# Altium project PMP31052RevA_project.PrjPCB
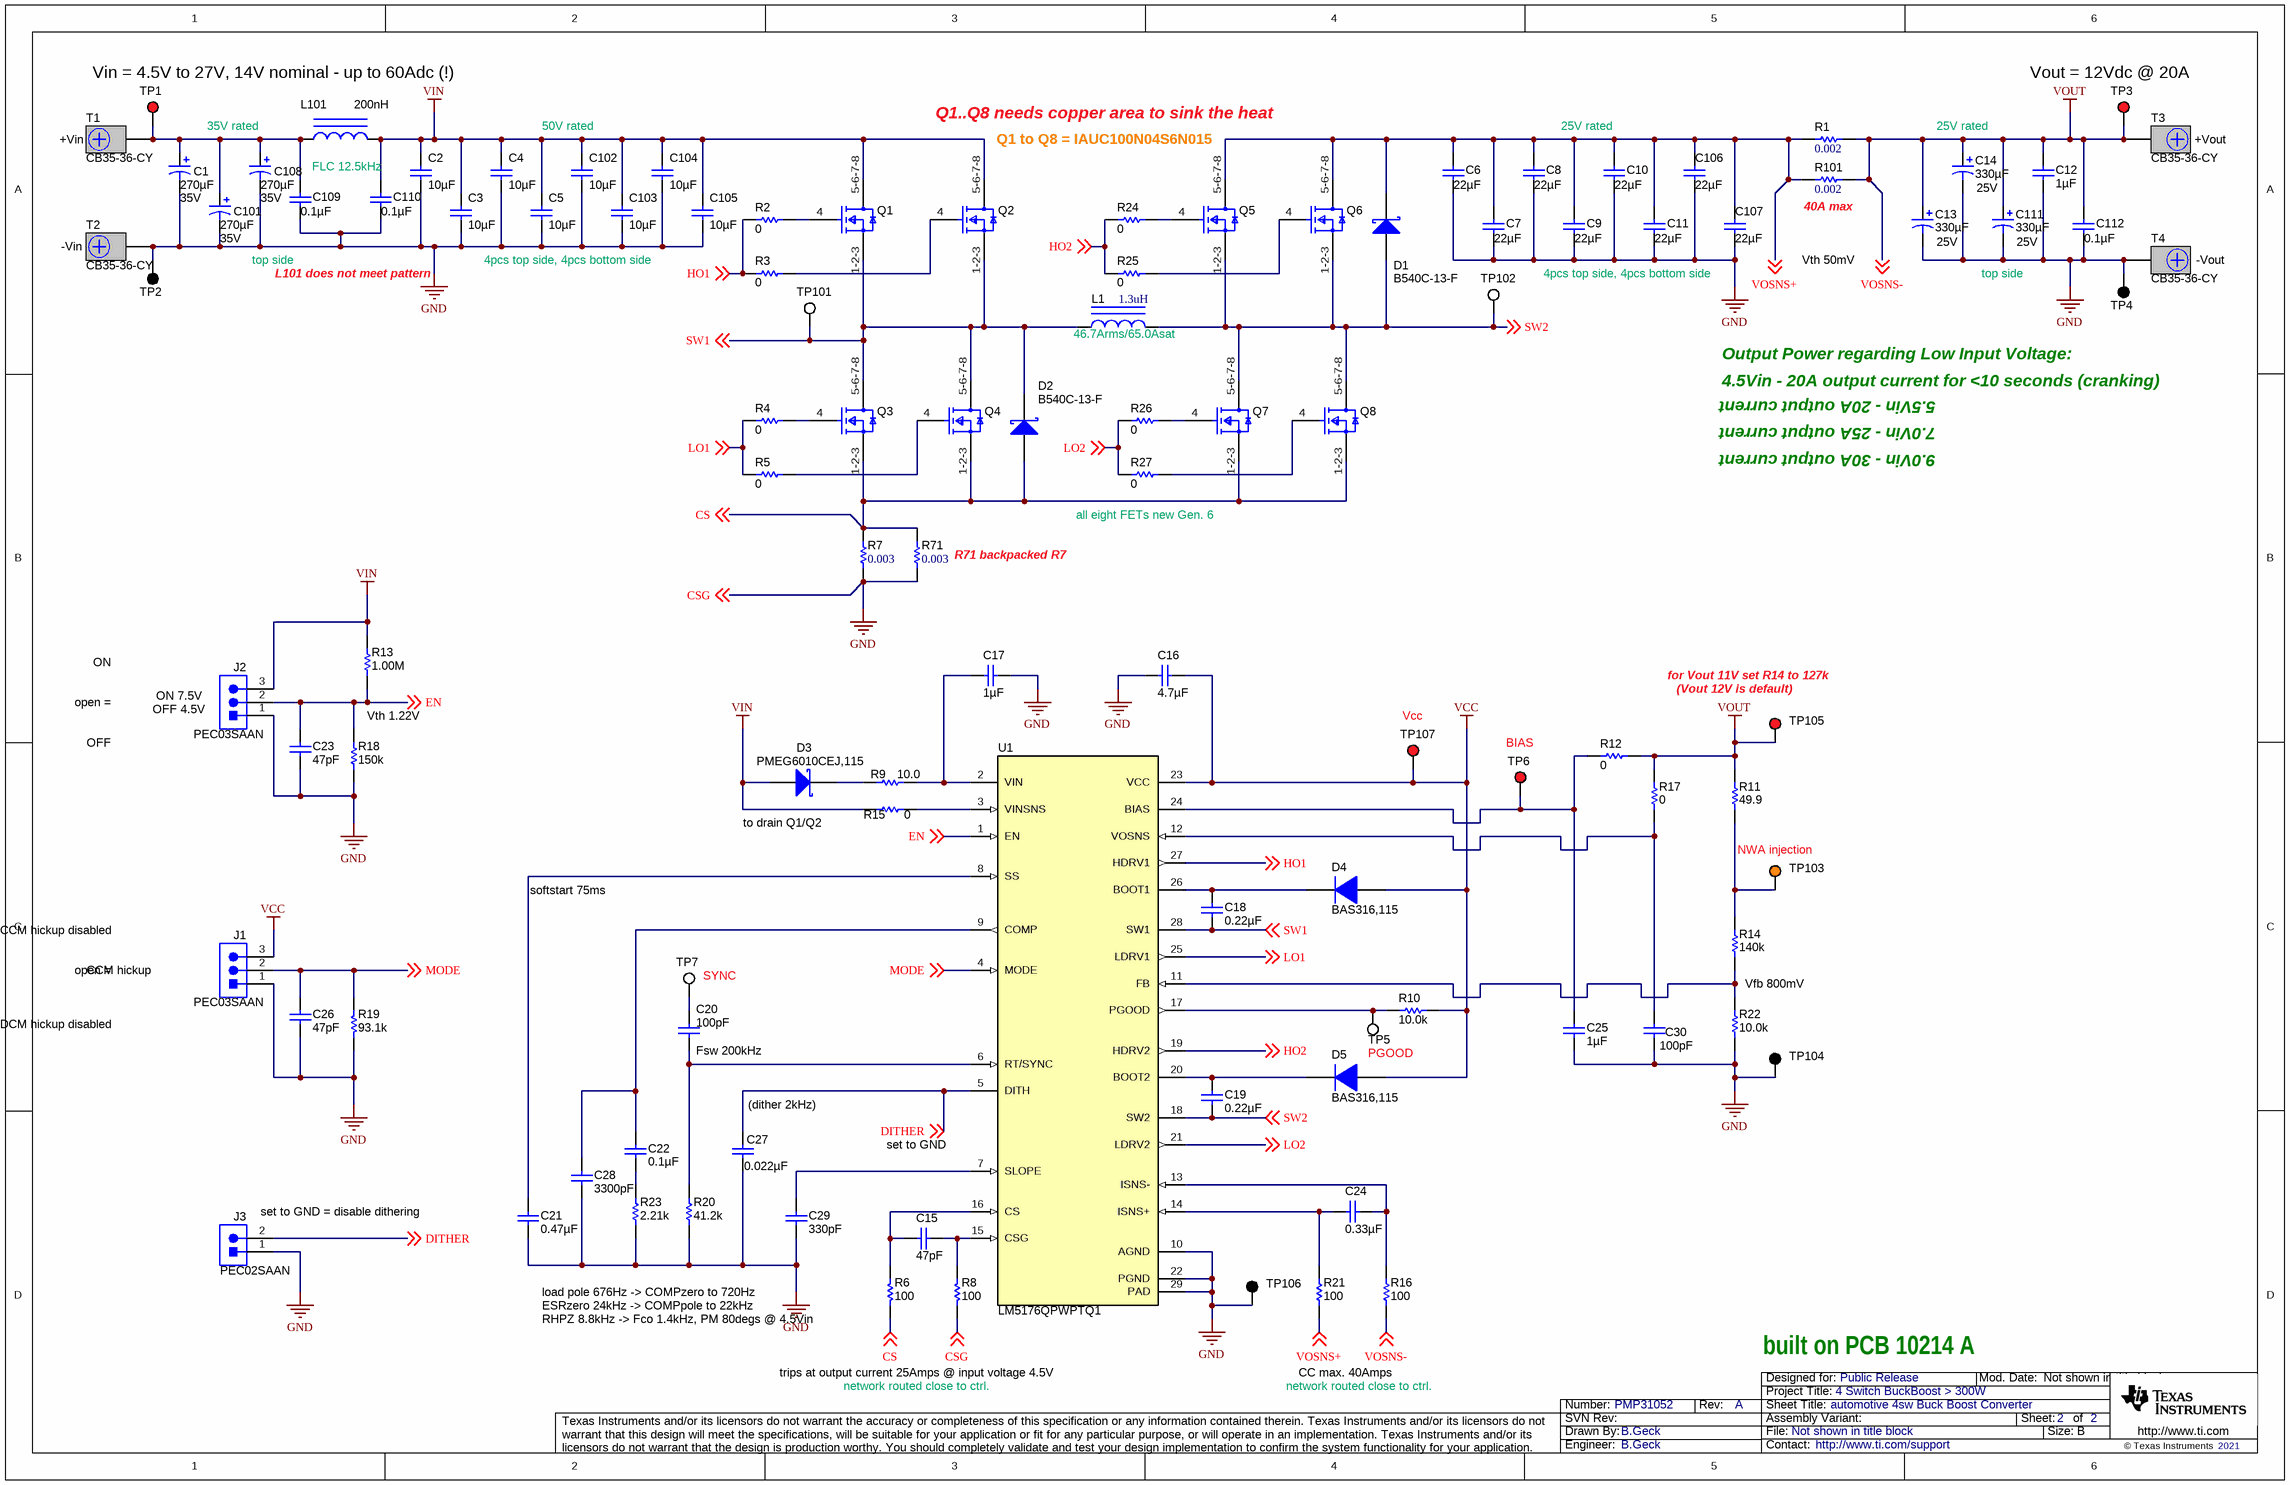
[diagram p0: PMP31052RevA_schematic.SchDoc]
TechSupport: http://www.ti.com/support; SCH_Rev: A; PRJ_Title: 4 Switch BuckBoost > 300W; PRJ_Number: PMP31052; PRJ_Engineer: B.Geck; PRJ_Customer: Public Release; PCB_Rev: A; PCB_Layout: PMP10214; CopyrightYear: 2021
2 sheets, 123 parts. Net scope: global (net labels, ports and power ports of the same name join across sheets).
Board file: PMP10214RevA_board.PcbDoc
Sheets:
  PMP31052RevA_schematic.SchDoc
  PMP31052RevA-HW.SchDoc

## Sheet PMP31052RevA_schematic.SchDoc: automotive 4sw Buck Boost Converter
size 431 x 279 mm; Date: Not shown in title block; ApprovedBy: Not shown in title block; CheckedBy: Not shown in title block; Author: Not shown in title block; CompanyName: Not shown in title block; DrawnBy: B.Geck; Engineer: B.Geck; Organization: Not shown in title block; Address1: Not shown in title block; Address2: Not shown in title block; Address3: Not shown in title block; Address4: Not shown in title block; DocumentNumber: 2; Revision: Use project parameter SCH_Rev; SheetNumber: 2; SheetTotal: 2; PageSetup: Record=PageOptions¦CenterHorizontal=True¦CenterVertical=True¦PrintScale=0.62¦XCorrection=1.00¦YCorrection=1.00¦PrintKind=0¦BorderSize=5000000¦LeftOffset=0¦BottomOffset=0¦Orientation=2¦PaperLength=1000¦PaperWidth=1000¦Scale=100¦PaperSource=15¦PrintQuality=600¦MediaType=1¦DitherType=10¦PrintScaleMode=1¦PaperKind=Letter

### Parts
C1  ValueDisplayed: 270µF  Value2: 35V  [SM_RADIAL_10BMM]  (hidden comment: EEHZC1V271P)
C2  ValueDisplayed: 10µF  [1210]  (hidden comment: GRM32ER71H106KA12L)
C3  ValueDisplayed: 10µF  [1210]  (hidden comment: GRM32ER71H106KA12L)
C4  ValueDisplayed: 10µF  [1210]  (hidden comment: GRM32ER71H106KA12L)
C5  ValueDisplayed: 10µF  [1210]  (hidden comment: GRM32ER71H106KA12L)
C6  ValueDisplayed: 22µF  [1210]  (hidden comment: GRM32ER71E226KE15L)
C7  ValueDisplayed: 22µF  [1210]  (hidden comment: GRM32ER71E226KE15L)
C8  ValueDisplayed: 22µF  [1210]  (hidden comment: GRM32ER71E226KE15L)
C9  ValueDisplayed: 22µF  [1210]  (hidden comment: GRM32ER71E226KE15L)
C10  ValueDisplayed: 22µF  [1210]  (hidden comment: GRM32ER71E226KE15L)
C11  ValueDisplayed: 22µF  [1210]  (hidden comment: GRM32ER71E226KE15L)
C12  ValueDisplayed: 1µF  [0805_HV]  (hidden comment: GRM219R71E105KA88D)
C13  ValueDisplayed: 330µF  Value2: 25V  [SM_RADIAL_10BMM]  (hidden comment: EEHZC1E331P)
C14  ValueDisplayed: 330µF  Value2: 25V  [SM_RADIAL_10BMM]  (hidden comment: EEHZC1E331P)
C15  ValueDisplayed: 47pF  [0603L]  (hidden comment: GRM1885C1H470JA01D)
C16  ValueDisplayed: 4.7µF  [0805_HV]  (hidden comment: GRM21BR71C475KA73L)
C17  ValueDisplayed: 1µF  [0603]  (hidden comment: GRM188R61H105KAALD)
C18  ValueDisplayed: 0.22µF  [0603L]  (hidden comment: GRM188R71E224KA88D)
C19  ValueDisplayed: 0.22µF  [0603L]  (hidden comment: GRM188R71E224KA88D)
C20  ValueDisplayed: 100pF  [0603L]  (hidden comment: GRM1885C2A101JA01D)
C21  ValueDisplayed: 0.47µF  [0603L]  (hidden comment: GRM188R71C474KA88D)
C22  ValueDisplayed: 0.1µF  [0603]  (hidden comment: GRM188R71E104KA01D)
C23  47pF  [0603L]
C24  ValueDisplayed: 0.33µF  [0603L]  (hidden comment: GRM188R71C334KA01D)
C25  ValueDisplayed: 1µF  [0603]  (hidden comment: GRM188R61H105KAALD)
C26  47pF  [0603L]
C27  ValueDisplayed: 0.022µF  [0603L]  (hidden comment: C0603C223K5RACTU)
C28  ValueDisplayed: 3300pF  [0603]  (hidden comment: GRM188R71E332KA01D)
C29  ValueDisplayed: 330pF  [0603]  (hidden comment: GRM188R71H331KA01D)
C30  ValueDisplayed: 100pF  [0603L]  (hidden comment: GRM1885C2A101JA01D)
C101  ValueDisplayed: 270µF  Value2: 35V  [SM_RADIAL_10BMM]  (hidden comment: EEHZC1V271P)
C102  ValueDisplayed: 10µF  [1210]  (hidden comment: GRM32ER71H106KA12L)
C103  ValueDisplayed: 10µF  [1210]  (hidden comment: GRM32ER71H106KA12L)
C104  ValueDisplayed: 10µF  [1210]  (hidden comment: GRM32ER71H106KA12L)
C105  ValueDisplayed: 10µF  [1210]  (hidden comment: GRM32ER71H106KA12L)
C106  ValueDisplayed: 22µF  [1210]  (hidden comment: GRM32ER71E226KE15L)
C107  ValueDisplayed: 22µF  [1210]  (hidden comment: GRM32ER71E226KE15L)
C108  ValueDisplayed: 270µF  Value2: 35V  [SM_RADIAL_10BMM]  (hidden comment: EEHZC1V271P)
C109  ValueDisplayed: 0.1µF  [0603L]  (hidden comment: GRM188R72A104KA35D)
C110  ValueDisplayed: 0.1µF  [0603L]  (hidden comment: GRM188R72A104KA35D)
C111  ValueDisplayed: 330µF  Value2: 25V  [SM_RADIAL_10BMM]  (hidden comment: EEHZC1E331P)
C112  ValueDisplayed: 0.1µF  [0603L]  (hidden comment: GRM188R72A104KA35D)
D1  B540C-13-F  [SMC]
D2  B540C-13-F  [SMC]
D3  PMEG6010CEJ,115  [SOD-323F]
D4  BAS316,115  [sod-323]
D5  BAS316,115  [sod-323]
J1  PEC03SAAN  [CONN_PEC03SAAN]
J2  PEC03SAAN  [CONN_PEC03SAAN]
J3  PEC02SAAN  [CONN_PEC02SAAN]
L1  ValueDisplayed: 1.3uH  [XAL1580]  (hidden comment: XAL1580-132MEB)
L101  ValueDisplayed: 200nH  [SLC1480]  (hidden comment: SLC1480-201MLB)
Q1  IAUC100N04S6N015ATMA1  [FP-IAUC120N04S6N009ATMA1_TDSON8-MFG]  (value not drawn)
Q2  IAUC100N04S6N015ATMA1  [FP-IAUC120N04S6N009ATMA1_TDSON8-MFG]  (value not drawn)
Q3  IAUC100N04S6N015ATMA1  [FP-IAUC120N04S6N009ATMA1_TDSON8-MFG]  (value not drawn)
Q4  IAUC100N04S6N015ATMA1  [FP-IAUC120N04S6N009ATMA1_TDSON8-MFG]  (value not drawn)
Q5  IAUC100N04S6N015ATMA1  [FP-IAUC120N04S6N009ATMA1_TDSON8-MFG]  (value not drawn)
Q6  IAUC100N04S6N015ATMA1  [FP-IAUC120N04S6N009ATMA1_TDSON8-MFG]  (value not drawn)
Q7  IAUC100N04S6N015ATMA1  [FP-IAUC120N04S6N009ATMA1_TDSON8-MFG]  (value not drawn)
Q8  IAUC100N04S6N015ATMA1  [FP-IAUC120N04S6N009ATMA1_TDSON8-MFG]  (value not drawn)
R1  ValueDisplayed: 0.002  [2512_WIDE]  (hidden comment: FCSL64R002GER)
R2  value 0  [0603L]  (hidden comment: RC0603JR-070RL)
R3  value 0  [0603L]  (hidden comment: RC0603JR-070RL)
R4  value 0  [0603L]  (hidden comment: RC0603JR-070RL)
R5  value 0  [0603L]  (hidden comment: RC0603JR-070RL)
R6  value 100  [0603_HV]  (hidden comment: RC0603FR-07100RL)
R7  ValueDisplayed: 0.003  [4320]  (hidden comment: KRL11050-C-R003-F-T1)
R8  value 100  [0603_HV]  (hidden comment: RC0603FR-07100RL)
R9  value 10.0  [0603L]  (hidden comment: RC0603FR-0710RL)
R10  value 10.0k  [0603L]  (hidden comment: RC0603FR-0710KL)
R11  ValueDisplayed: 49.9  [0603]  (hidden comment: CRCW060349R9FKEA)
R12  value 0  [0603L]  (hidden comment: RC0603JR-070RL)
R13  ValueDisplayed: 1.00M  [0603]  (hidden comment: CRCW06031M00FKEA)
R14  ValueDisplayed: 140k  [0603]  (hidden comment: CRCW0603140KFKEA)
R15  value 0  [0603L]  (hidden comment: RC0603JR-070RL)
R16  100  [0603L]
R17  value 0  [0603L]  (hidden comment: RC0603JR-070RL)
R18  ValueDisplayed: 150k  [0603]  (hidden comment: CRCW0603150KFKEA)
R19  ValueDisplayed: 93.1k  [0603L]  (hidden comment: RC0603FR-0793K1L)
R20  ValueDisplayed: 41.2k  [0603]  (hidden comment: CRCW060341K2FKEA)
R21  100  [0603L]
R22  ValueDisplayed: 10.0k  [0603]  (hidden comment: CRCW060310K0FKEA)
R23  ValueDisplayed: 2.21k  [0603]  (hidden comment: CRCW06032K21FKEA)
R24  value 0  [0603L]  (hidden comment: RC0603JR-070RL)
R25  value 0  [0603L]  (hidden comment: RC0603JR-070RL)
R26  value 0  [0603L]  (hidden comment: RC0603JR-070RL)
R27  value 0  [0603L]  (hidden comment: RC0603JR-070RL)
R71  ValueDisplayed: 0.003  [4320]  (hidden comment: KRL11050-C-R003-F-T1)
R101  ValueDisplayed: 0.002  [2512_WIDE]  (hidden comment: FCSL64R002GER)
T1  CB35-36-CY  [CB35-36-CY]
T2  CB35-36-CY  [CB35-36-CY]
T3  CB35-36-CY  [CB35-36-CY]
T4  CB35-36-CY  [CB35-36-CY]
TP1  5005  [Keystone5005]  (value not drawn)
TP2  5006  [Keystone5006]  (value not drawn)
TP3  5005  [Keystone5005]  (value not drawn)
TP4  5006  [Keystone5006]  (value not drawn)
TP5  value PGOOD  [Keystone5007]  (hidden comment: 5007)
TP6  5000  [Keystone5000]  (value not drawn)
TP7  SYNC  [Keystone5007]
TP101  5002  [Keystone5002]  (value not drawn)
TP102  5002  [Keystone5002]  (value not drawn)
TP103  5003  [Keystone5003]  (value not drawn)
TP104  5001  [Keystone5001]  (value not drawn)
TP105  5000  [Keystone5000]  (value not drawn)
TP106  5001  [Keystone5001]  (value not drawn)
TP107  5000  [Keystone5000]  (value not drawn)
U1  LM5176QPWPTQ1  [PWP0028C_N]

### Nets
GND: C1.2(-) C2.2 C3.2 C4.2 C5.2 C6.2 C7.2 C8.2 C9.2 C10.2 C11.2 C12.2 C13.2(-) C14.2(-) C16.1 C17.2 C21.2 C23.2 C25.2 C26.2 C27.2 C28.2 C29.2 C30.2 C101.2(-) C102.2 C103.2 C104.2 C105.2 C106.2 C107.2 C108.2(-) C109.2 C110.2 C111.2(-) C112.2 J1.1 J2.1 J3.1 R7.1 R8.1 R18.1 R19.1 R20.1 R22.1 R23.1 R71.1 T2.1 T4.1 TP2.1 TP4.1 TP104.1 TP106.1 U1.10(AGND) U1.22(PGND) U1.29(PAD) ; off-sheet CSG  [also labelled CSG]
VCC: C16.2 D4.2(A) D5.2(A) J1.3 R10.2 TP107.1 U1.23(VCC)
VIN: C2.1 C3.1 C4.1 C5.1 C102.1 C103.1 C104.1 C105.1 C110.1 D3.2(A) J2.3 L101.2 Q1.5-6-7-8(D) Q2.5-6-7-8(D) R13.2 R15.2
VOUT: C12.1 C13.1(+) C14.1(+) C111.1(+) C112.1 R1.2 R11.2 R12.2 R16.1 R17.1 R101.2 T3.1 TP3.1 TP105.1 ; off-sheet VOSNS-  [also labelled VOSNS-]
CS: D2.2(A) Q3.1-2-3(S) Q4.1-2-3(S) Q7.1-2-3(S) Q8.1-2-3(S) R6.1 R7.2 R71.2 ; off-sheet CS
DITHER: C27.1 J3.2 U1.5(DITH) ; off-sheet DITHER
EN: C23.1 J2.2 R13.1 R18.2 U1.1(EN) ; off-sheet EN
HO1: R2.2 R3.2 U1.27(HDRV1) ; off-sheet HO1
HO2: R24.2 R25.2 U1.19(HDRV2) ; off-sheet HO2
LO1: R4.2 R5.2 U1.25(LDRV1) ; off-sheet LO1
LO2: R26.2 R27.2 U1.21(LDRV2) ; off-sheet LO2
MODE: C26.1 J1.2 R19.2 U1.4(MODE) ; off-sheet MODE
SW1: C18.1 D2.1(K) L1.1 Q1.1-2-3(S) Q2.1-2-3(S) Q3.5-6-7-8(D) Q4.5-6-7-8(D) TP101.1 U1.28(SW1) ; off-sheet SW1
SW2: C19.2 D1.2(A) L1.2 Q5.1-2-3(S) Q6.1-2-3(S) Q7.5-6-7-8(D) Q8.5-6-7-8(D) TP102.1 U1.18(SW2) ; off-sheet SW2
VOSNS+: C6.1 C7.1 C8.1 C9.1 C10.1 C11.1 C106.1 C107.1 D1.1(K) Q5.5-6-7-8(D) Q6.5-6-7-8(D) R1.1 R21.1 R101.1 ; off-sheet VOSNS+
NetC1_1: C1.1(+) C101.1(+) C108.1(+) C109.1 L101.1 T1.1 TP1.1
NetC15_1: C15.1 R6.2 U1.16(CS)
NetC15_2: C15.2 R8.2 U1.15(CSG)
NetC17_1: C17.1 R9.1 U1.2(VIN)
NetC18_2: C18.2 D4.1(K) U1.26(BOOT1)
NetC19_1: C19.1 D5.1(K) U1.20(BOOT2)
NetC20_1: C20.1 R20.2 U1.6(RT/SYNC)
NetC20_2: C20.2 TP7.1
NetC21_1: C21.1 U1.8(SS)
NetC22_1: C22.1 C28.1 U1.9(COMP)
NetC22_2: C22.2 R23.2
NetC24_1: C24.1 R21.2 U1.14(ISNS+)
NetC24_2: C24.2 R16.2 U1.13(ISNS-)
NetC25_1: C25.1 R12.1 TP6.1 U1.24(BIAS)
NetC29_1: C29.1 U1.7(SLOPE)
NetC30_1: C30.1 R17.2 U1.12(VOSNS)
NetD3_1: D3.1(K) R9.2
NetQ1_4: Q1.4(G) R2.1
NetQ2_4: Q2.4(G) R3.1
NetQ3_4: Q3.4(G) R4.1
NetQ4_4: Q4.4(G) R5.1
NetQ5_4: Q5.4(G) R24.1
NetQ6_4: Q6.4(G) R25.1
NetQ7_4: Q7.4(G) R26.1
NetQ8_4: Q8.4(G) R27.1
NetR10_1: R10.1 TP5.1 U1.17(PGOOD)
NetR11_1: R11.1 R14.2 TP103.1
NetR14_1: R14.1 R22.2 U1.11(FB)
NetR15_1: R15.1 U1.3(VINSNS)

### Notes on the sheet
- (near TP1) Vin = 4.5V to 27V, 14V nominal - up to 60Adc (!)
- (near TP3) Vout = 12Vdc @ 20A
- (near T1) +Vin
- 35V rated
- FLC 12.5kHz
- 50V rated
- Q1 to Q8 = IAUC100N04S6N015
- Q1..Q8 needs copper area to sink the heat
- 25V rated
- (near C14) 25V rated
- (near T3) +Vout
- (near R101) 40A max
- (near T2) -Vin
- top side
- L101 does not meet pattern
- 4pcs top side, 4pcs bottom side
- Vth 50mV
- (near C111) top side
- (near T4) -Vout
- (near L1) 46.7Arms/65.0Asat
- Output Power regarding Low Input Voltage:
- 4.5Vin - 20A output current for <10 seconds (cranking)
- 5.5Vin - 20A output current
- 7.0Vin - 25A output current
- 9.0Vin - 30A output current
- (near R71) R71 backpacked R7
- (near R27) all eight FETs new Gen. 6
- ON
- open =
- (near J2) ON 7.5V
- (near J2) OFF 4.5V
- (near TP105) (Vout 12V is default)
- (near TP105) for Vout 11V set R14 to 127k
- OFF
- Vth 1.22V
- (near TP107) Vcc
- (near TP6) BIAS
- to drain Q1/Q2
- softstart 75ms
- NWA injection
- (near J1) CCM hickup disabled
- (near J1) CCM hickup
- (near J1) DCM hickup disabled
- Vfb 800mV
- (near C20) Fsw 200kHz
- (near C27) (dither 2kHz)
- (near U1) set to GND
- (near J3) set to GND = disable dithering
- load pole 676Hz -> COMPzero to 720Hz
- ESRzero 24kHz -> COMPpole to 22kHz
- RHPZ 8.8kHz -> Fco 1.4kHz, PM 80degs @ 4.5Vin
- trips at output current 25Amps @ input voltage 4.5V
- CC max. 40Amps
- built on PCB 10214 A
- network routed close to ctrl.

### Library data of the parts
C1 C101 C108 = EEHZC1V271P: CAP, Polymer Hybrid, 270 µF, 35 V,+/- 20%, 20 ohm, 10x10 SMD; Manufacturer: Panasonic; Polarized: Y; CompType: Capacitor; Value: 270uF; U/M: EA; Cap_F: 0.00027; Tolerance_%: 20; Value1: 20 ohm; VDC_V: 35; IRMS_A: 2; TaMin_C: -55; TaMax_C: 125; SizeAreaWB_mm2: 159.9; SizeArea_mm2: 113.3; SizeX_mm: 11; SizeY_mm: 10.3; SizeZ_mm: 10.2; AEC Category: Q200
C2-C5 C102-C105 = GRM32ER71H106KA12L: CAP, CERM, 10 µF, 50 V, +/- 10%, X7R, 1210; Manufacturer: MuRata; CompType: Capacitor; Value: 10uF; U/M: EA; Tolerance_%: 10; VDC_V: 50; Polarized: N; Cap_F: 0.00001; Value1: Unknown; Value2: 50V; TaMin_C: -55; TaMax_C: 125
C6-C11 C106 C107 = GRM32ER71E226KE15L: CAP, CERM, 22 µF, 25 V, +/- 10%, X7R, 1210; Manufacturer: MuRata; Polarized: N; CompType: Capacitor; Value: 22uF; U/M: EA; Cap_F: 0.000022; Tolerance_%: 10; Value1: Unknown; VDC_V: 25; Value2: 25V; TaMin_C: -55; TaMax_C: 125
C12 = GRM219R71E105KA88D: CAP, CERM, 1 µF, 25 V, +/- 10%, X7R, 0805; Manufacturer: MuRata; Polarized: N; CompType: Capacitor; Value: 1uF; U/M: EA; Cap_F: 0.000001; Tolerance_%: 10; Value1: Unknown; VDC_V: 25; Value2: 25V; TaMin_C: -55; TaMax_C: 125; Cap_Case: 0805
C13 C14 C111 = EEHZC1E331P: CAP, Polymer Hybrid, 330 µF, 25 V,+/- 20%, 20 ohm, 10x10 SMD; Manufacturer: Panasonic; Polarized: Y; CompType: Capacitor; Value: 330uF; U/M: EA; Cap_F: 0.00033; Tolerance_%: 20; Value1: 20 ohm; VDC_V: 25; IRMS_A: 2; TaMin_C: -55; TaMax_C: 125; SizeAreaWB_mm2: 159.9; SizeArea_mm2: 113.3; SizeX_mm: 11; SizeY_mm: 10.3; SizeZ_mm: 10.2; AEC Category: Q200
C15 C23 C26 = GRM1885C1H470JA01D: CAP, CERM, 47pF, 50V, +/-5%, C0G/NP0, 0603; Manufacturer: MuRata; Polarized: N; CompType: Capacitor; U/M: EA; Cap_F: 0.000000000047; Tolerance_%: 5; Value1: Unknown; VDC_V: 50; TaMin_C: -55; TaMax_C: 125; Cap_Case: 0603
C16 = GRM21BR71C475KA73L: CAP, CERM, 4.7 µF, 16 V, +/- 10%, X7R, 0805; Manufacturer: MuRata; Polarized: N; CompType: Capacitor; Value: 4.7uF; U/M: EA; Cap_F: 0.0000047; Tolerance_%: 10; ESR_ohm: 0.006; Value1: 0.006 ohm; VDC_V: 16; Value2: 16V; TaMin_C: -55; TaMax_C: 125; Cap_Case: 0805
C17 C25 = GRM188R61H105KAALD: CAP, CERM, 1 µF, 50 V, +/- 10%, X5R, 0603; Manufacturer: MuRata; Polarized: N; CompType: Capacitor; Value: 1uF; U/M: EA; Cap_F: 0.000001; Tolerance_%: 10; Value1: Unknown; VDC_V: 50; Value2: 50V; TaMin_C: -55; TaMax_C: 85
C18 C19 = GRM188R71E224KA88D: CAP, CERM, 0.22 µF, 25 V, +/- 10%, X7R, 0603; Manufacturer: MuRata; Polarized: N; CompType: Capacitor; Value: 0.22uF; U/M: EA; Cap_F: 0.00000022; Tolerance_%: 10; Value1: Unknown; VDC_V: 25; Value2: 25V; TaMin_C: -55; TaMax_C: 125; Cap_Case: 0603
C20 C30 = GRM1885C2A101JA01D: CAP, CERM, 100pF, 100V, +/-5%, C0G/NP0, 0603; Manufacturer: MuRata; Polarized: N; CompType: Capacitor; U/M: EA; Cap_F: 0.0000000001; Tolerance_%: 5; Value1: Unknown; VDC_V: 100; TaMin_C: -55; TaMax_C: 125; Cap_Case: 0603
C21 = GRM188R71C474KA88D: CAP, CERM, 0.47 µF, 16 V, +/- 10%, X7R, 0603; Manufacturer: MuRata; Polarized: N; CompType: Capacitor; Value: 0.47uF; U/M: EA; Cap_F: 0.00000047; Tolerance_%: 10; Value1: Unknown; VDC_V: 16; Value2: 16V; TaMin_C: -55; TaMax_C: 125; Cap_Case: 0603; AEC Category: Q200
C22 = GRM188R71E104KA01D: CAP, CERM, 0.1 µF, 25 V,+/- 10%, X7R, 0603; Manufacturer: MuRata; Polarized: N; CompType: Capacitor; Value: 0.1uF; U/M: EA; Cap_F: 0.0000001; Tolerance_%: 10; VDC_V: 25; Value2: 25V; TaMin_C: -55; TaMax_C: 125; SizeArea_mm2: 1.28; SizeAreaWB_mm2: 4.68; SizeX_mm: 1.6; SizeY_mm: 0.8; SizeZ_mm: 1; AEC Category: Q200; Green_Lifecycle: Active; Green_REACh: Passed
C24 = GRM188R71C334KA01D: CAP, CERM, 0.33 µF, 16 V, +/- 10%, X7R, 0603; Manufacturer: MuRata; Polarized: N; CompType: Capacitor; Value: 0.33uF; U/M: EA; Cap_F: 0.00000033; Tolerance_%: 10; Value1: Unknown; VDC_V: 16; Value2: 16V; TaMin_C: -55; TaMax_C: 125; Cap_Case: 0603
C27 = C0603C223K5RACTU: CAP, CERM, 0.022uF, 50V, +/-10%, X7R, 0603; Manufacturer: Kemet; Polarized: N; CompType: Capacitor; U/M: EA; Cap_F: 0.000000022; Tolerance_%: 10; Value1: Unknown; VDC_V: 50; TaMin_C: -55; TaMax_C: 125; Cap_Case: 0603
C28 = GRM188R71E332KA01D: CAP, CERM, 3300 pF, 25 V,+/- 10%, X7R, 0603; Manufacturer: MuRata; Polarized: N; CompType: Capacitor; Value: 3300pF; U/M: EA; Cap_F: 0.0000000033; Tolerance_%: 10; VDC_V: 25; Value2: 25V; TaMin_C: -55; TaMax_C: 125; SizeArea_mm2: 1.28; SizeAreaWB_mm2: 4.68; SizeX_mm: 1.6; SizeY_mm: 0.8; SizeZ_mm: 1; AEC Category: Q200; Green_Lifecycle: Active; Green_REACh: Passed
C29 = GRM188R71H331KA01D: CAP, CERM, 330 pF, 50 V,+/- 10%, X7R, 0603; Manufacturer: MuRata; Polarized: N; CompType: Capacitor; Value: 330pF; U/M: EA; Cap_F: 0.00000000033; Tolerance_%: 10; VDC_V: 50; Value2: 50V; TaMin_C: -55; TaMax_C: 125; SizeArea_mm2: 1.28; SizeAreaWB_mm2: 4.68; SizeX_mm: 1.6; SizeY_mm: 0.8; SizeZ_mm: 1; AEC Category: Q200; Green_Lifecycle: Active; Green_REACh: Passed
C109 C110 C112 = GRM188R72A104KA35D: CAP, CERM, 0.1uF, 100V, +/-10%, X7R, 0603; Manufacturer: MuRata; Polarized: N; CompType: Capacitor; U/M: EA; Cap_F: 0.0000001; Tolerance_%: 10; Value1: Unknown; VDC_V: 100; TaMin_C: -55; TaMax_C: 125; Cap_Case: 0603
D1 D2 = B540C-13-F: Diode, Schottky, 40 V, 5 A, SMC; Manufacturer: Diodes Inc.; U/M: EA; Vf_V: 0.55; Value: 40V; Value1: 5A; Value2: 0.55V; Io_A: 5; Vr_V: 40; TJmax_C: 125; RJC_CperW: 10; SizeAreaWB_mm2: 83.2686; SizeArea_mm2: 50.5686; SizeX_mm: 8.13; SizeY_mm: 6.22; SizeZ_mm: 2.6; AEC Category: Q101; Green_Lifecycle: Active; Green_REACh: Passed
D3 = PMEG6010CEJ,115: Diode, Schottky, 60 V, 1 A, SOD-323F; Manufacturer: NXP Semiconductor; U/M: EA; Vf_V: 0.66; Value: 60V; Value1: 1A; Value2: 0.66V; Io_A: 1; Vr_V: 60; TJmax_C: 150
D4 D5 = BAS316,115: Diode, Ultrafast, 100V, 0.25A, SOD-323; Manufacturer: NXP Semiconductor; U/M: EA; Vr_V: 100; Io_A: 0.25; Vf_V: 1.4; Value2: 1.4V; TJmax_C: 150
J1 J2 = PEC03SAAN: Header, 100mil, 3x1, Tin, TH; Manufacturer: Sullins Connector Solutions; SymbolCreator: a0799628; U/M: EA
J3 = PEC02SAAN: Header, 100mil, 2x1, Tin, TH; Manufacturer: Sullins Connector Solutions; SymbolCreator: a0412235; U/M: EA
L1 = CMP-0060974-1: Inductor, Shielded, Composite, 1.3 uH, 46.7 A, 0.00115 ohm, SMD; Manufacturer: Coilcraft; Isat: 65A @ 0.7% inductance drop; Irms: 46.7A @ 40C rise; Green_Lifecycle: Not Set; SizeAreaWB_mm2: 313.04; DCR_ohm: 1.15m; Green_REACh: Incomplete; Value: 1.3uH; Imax_A: 46.7A; SizeZ_mm: 8; SizeX_mm: 15.2; SizeY_mm: 16.2; SizeArea_mm2: 246.24; Ind_H: 1.3µH; AEC Category: Q200
L101 = SLC1480-201MLB: Inductor, Shielded, Ferrite, 200 nH, 55 A, 0.00015 ohm, SMD; Manufacturer: Coilcraft; Value: 200nH; Ind_H: 200.0E-9; Imax_A: 55; Irms: 55A @ 40C rise; Isat: 76A @ 30% inductance drop; Value2: 55A; SizeAreaWB_mm2: 231.127; SizeArea_mm2: 174.307; SizeX_mm: 13.46; SizeY_mm: 12.95; SizeZ_mm: 8; AEC Category: Q200; Green_Lifecycle: Not Set; Green_REACh: Incomplete
Q1-Q8 = CMP-0086959-1: Trans Mosfet N-ch 40V 100A 8-PIN Pg-tdson T/R; Manufacturer: Infineon; SizeZ_mm: 1.1mm; Rdson10_ohm: 1.55; QgTyp_nC: 42nC @ 10V; Vgs_V: 20V; AEC Qualified: Yes; ChMode: False
R1 R101 = FCSL64R002GER: RES, 0.002, 2%, 2 W, 2512 WIDE; Manufacturer: Ohmite; CompType: Resistor; Value: 0.002; Value_Code: 2L000; Tolerance_%: 2; Value2: 2W; TempCo: 100 ppm/C; SizeArea_mm2: 20.16; SizeAreaWB_mm2: 43.16; SizeX_mm: 3.2; SizeY_mm: 6.3; SizeZ_mm: 0.7; U/M: EA; AEC Category: Q200
R2-R5 R12 R15 R17 R24-R27 = RC0603JR-070RL: RES, 0 ohm, 5%, 0.1W, 0603; Manufacturer: Yageo America; CompType: Resistor; Value_Code: 0000; Tolerance_%: 5; Power_W: 0.1; VDC_V: 50; TempCo: 200 ppm/C; EIA_Code: E24; U/M: EA
R6 R8 R16 R21 = RC0603FR-07100RL: RES, 100 ohm, 1%, 0.1W, 0603; Manufacturer: Yageo America; CompType: Resistor; Value_Code: 100R; Tolerance_%: 1; Power_W: 0.1; VDC_V: 150; TempCo: 200 ppm/C; EIA_Code: E96; U/M: EA
R7 R71 = KRL11050-C-R003-F-T1: RES, 0.003, 1%, 6 W, 4320_WIDE; Manufacturer: Susumu Co Ltd; CompType: Resistor; Value: 0.003; Value_Code: 3L000; Tolerance_%: 1; Power_W: 6; Value2: 6W; TempCo: 50 ppm/C; EIA_Code: E96; U/M: EA; AEC Category: Q200
R9 = RC0603FR-0710RL: RES, 10.0 ohm, 1%, 0.1W, 0603; Manufacturer: Yageo America; CompType: Resistor; Res_ohm: 10; Value_Code: 10R0; Tolerance_%: 1; Power_W: 0.1; VDC_V: 150; TempCo: 200 ppm/C; EIA_Code: E96; U/M: EA
R10 = RC0603FR-0710KL: RES, 10.0k ohm, 1%, 0.1W, 0603; Manufacturer: Yageo America; CompType: Resistor; Res_ohm: 10000; Value_Code: 10k0; Tolerance_%: 1; Power_W: 0.1; VDC_V: 150; TempCo: 200 ppm/C; EIA_Code: E96; U/M: EA
R11 = CRCW060349R9FKEA: RES, 49.9, 1%, 0.1 W, 0603; Manufacturer: Vishay-Dale; CompType: Resistor; Value: 49.9; Value_Code: 49R9; Tolerance_%: 1; Power_W: 0.1; Value2: 0.1W; VDC_V: 75; TempCo: 100 ppm/C; EIA_Code: E96; U/M: EA
R13 = CRCW06031M00FKEA: RES, 1.00 M, 1%, 0.1 W, 0603; Manufacturer: Vishay-Dale; CompType: Resistor; Value: 1.00Meg; Res_ohm: 1000000; Value_Code: 1M00; Tolerance_%: 1; Power_W: 0.1; Value2: 0.1W; VDC_V: 75; TempCo: 100 ppm/C; SizeArea_mm2: 1.28; SizeX_mm: 1.6; SizeY_mm: 0.8; EIA_Code: E96; U/M: EA; AEC Category: Q200; Green_Lifecycle: Active; Green_REACh: Passed
R14 = CRCW0603140KFKEA: RES, 140 k, 1%, 0.1 W, 0603; Manufacturer: Vishay-Dale; CompType: Resistor; Value: 140k; Res_ohm: 140000; Tolerance_%: 1; Power_W: 0.1; Value2: 0.1W; VDC_V: 75; TempCo: 100 ppm/C; SizeArea_mm2: 1.28; SizeX_mm: 1.6; SizeY_mm: 0.8; EIA_Code: E96; U/M: EA; AEC Category: Q200; Green_Lifecycle: Active; Green_REACh: Passed
R18 = CRCW0603150KFKEA: RES, 150 k, 1%, 0.1 W, 0603; Manufacturer: Vishay-Dale; CompType: Resistor; Value: 150k; Res_ohm: 150000; Tolerance_%: 1; Power_W: 0.1; Value2: 0.1W; VDC_V: 75; TempCo: 100 ppm/C; SizeArea_mm2: 1.28; SizeX_mm: 1.6; SizeY_mm: 0.8; EIA_Code: E96; U/M: EA; AEC Category: Q200; Green_Lifecycle: Active; Green_REACh: Passed
R19 = RC0603FR-0793K1L: RES, 93.1 k, 1%, 0.1 W, 0603; Manufacturer: Yageo America; CompType: Resistor; Value: 93.1k; Res_ohm: 93100; Value_Code: 93k1; Tolerance_%: 1; Power_W: 0.1; Value2: 0.1W; VDC_V: 150; TempCo: 200 ppm/C; EIA_Code: E96; U/M: EA
R20 = CRCW060341K2FKEA: RES, 41.2 k, 1%, 0.1 W, 0603; Manufacturer: Vishay-Dale; CompType: Resistor; Value: 41.2k; Res_ohm: 41200; Value_Code: 41k2; Tolerance_%: 1; Power_W: 0.1; Value2: 0.1W; VDC_V: 75; TempCo: 100 ppm/C; SizeArea_mm2: 1.28; SizeX_mm: 1.6; SizeY_mm: 0.8; EIA_Code: E96; U/M: EA; AEC Category: Q200
R22 = CRCW060310K0FKEA: RES, 10.0 k, 1%, 0.1 W, 0603; Manufacturer: Vishay-Dale; CompType: Resistor; Value: 10.0k; Res_ohm: 10000; Value_Code: 10k0; Tolerance_%: 1; Power_W: 0.1; Value2: 0.1W; VDC_V: 75; TempCo: 100 ppm/C; SizeArea_mm2: 1.28; SizeX_mm: 1.6; SizeY_mm: 0.8; EIA_Code: E96; U/M: EA; AEC Category: Q200; Green_Lifecycle: Active; Green_REACh: Passed
R23 = CRCW06032K21FKEA: RES, 2.21 k, 1%, 0.1 W, 0603; Manufacturer: Vishay-Dale; CompType: Resistor; Value: 2.21k; Res_ohm: 2210; Value_Code: 2k21; Tolerance_%: 1; Power_W: 0.1; Value2: 0.1W; VDC_V: 75; TempCo: 100 ppm/C; SizeArea_mm2: 1.28; SizeX_mm: 1.6; SizeY_mm: 0.8; EIA_Code: E96; U/M: EA; AEC Category: Q200; Green_Lifecycle: Active; Green_REACh: Passed
T1-T4 = CB35-36-CY: Terminal 50A Lug; Manufacturer: Panduit; SymbolCreator: crossc; CompType: Screw Terminal; U/M: EA
TP1 TP3 = 5005: Test Point, Compact, Red, TH; Manufacturer: Keystone; CompType: Test Point Loop; U/M: EA
TP2 TP4 = 5006: Test Point, Compact, Black, TH; Manufacturer: Keystone; CompType: Test Point Loop; U/M: EA
TP5 TP7 = 5007: Test Point, Compact, White, TH; Manufacturer: Keystone; CompType: Test Point Loop; U/M: EA
TP6 TP105 TP107 = 5000: Test Point, Miniature, Red, TH; Manufacturer: Keystone; CompType: Test Point Loop; U/M: EA
TP101 TP102 = 5002: Test Point, Miniature, White, TH; Manufacturer: Keystone; CompType: Test Point Loop; U/M: EA
TP103 = 5003: Test Point, Miniature, Orange, TH; Manufacturer: Keystone; CompType: Test Point Loop; U/M: EA
TP104 TP106 = 5001: Test Point, Miniature, Black, TH; Manufacturer: Keystone; CompType: Test Point Loop; U/M: EA
U1 = CMP-0860005-1: 55-V wide VIN synchronous 4-switch buck-boost controller, PWP0028C (HTSSOP-28); Alternate PartNumber: LM5176QPWPRQ1; Manufacturer: Texas Instruments; SizeAreaWB_mm2: 98.28; SizeY_mm: 9.7; Rating: Automotive; SizeZ_mm: 1.2; SizeX_mm: 6.4; AEC Qualified: Y; CompType: IC; SizeArea_mm2: 62.08; AEC Category: Q200

## Sheet PMP31052RevA-HW.SchDoc: LM5175EVM-HP HARDWARE
size 431 x 279 mm; Date: Not shown in title block; ApprovedBy: Not shown in title block; CheckedBy: Not shown in title block; Author: Not shown in title block; CompanyName: Not shown in title block; DrawnBy: a0413446; Engineer: Not shown in title block; Organization: Not shown in title block; Address1: Not shown in title block; Address2: Not shown in title block; Address3: Not shown in title block; Address4: Not shown in title block; DocumentNumber: 1; Revision: Use project parameter SCH_Rev; SheetNumber: 1; SheetTotal: 2; PageSetup: Record=PageOptions¦CenterHorizontal=True¦CenterVertical=True¦PrintScale=1.00¦XCorrection=1.00¦YCorrection=1.00¦PrintKind=0¦BorderSize=5000000¦LeftOffset=0¦BottomOffset=0¦Orientation=2¦PaperLength=1000¦PaperWidth=1000¦Scale=100¦PaperSource=15¦PrintQuality=600¦MediaType=1¦DitherType=10¦PaperKind=Letter¦PrintScaleMode=1
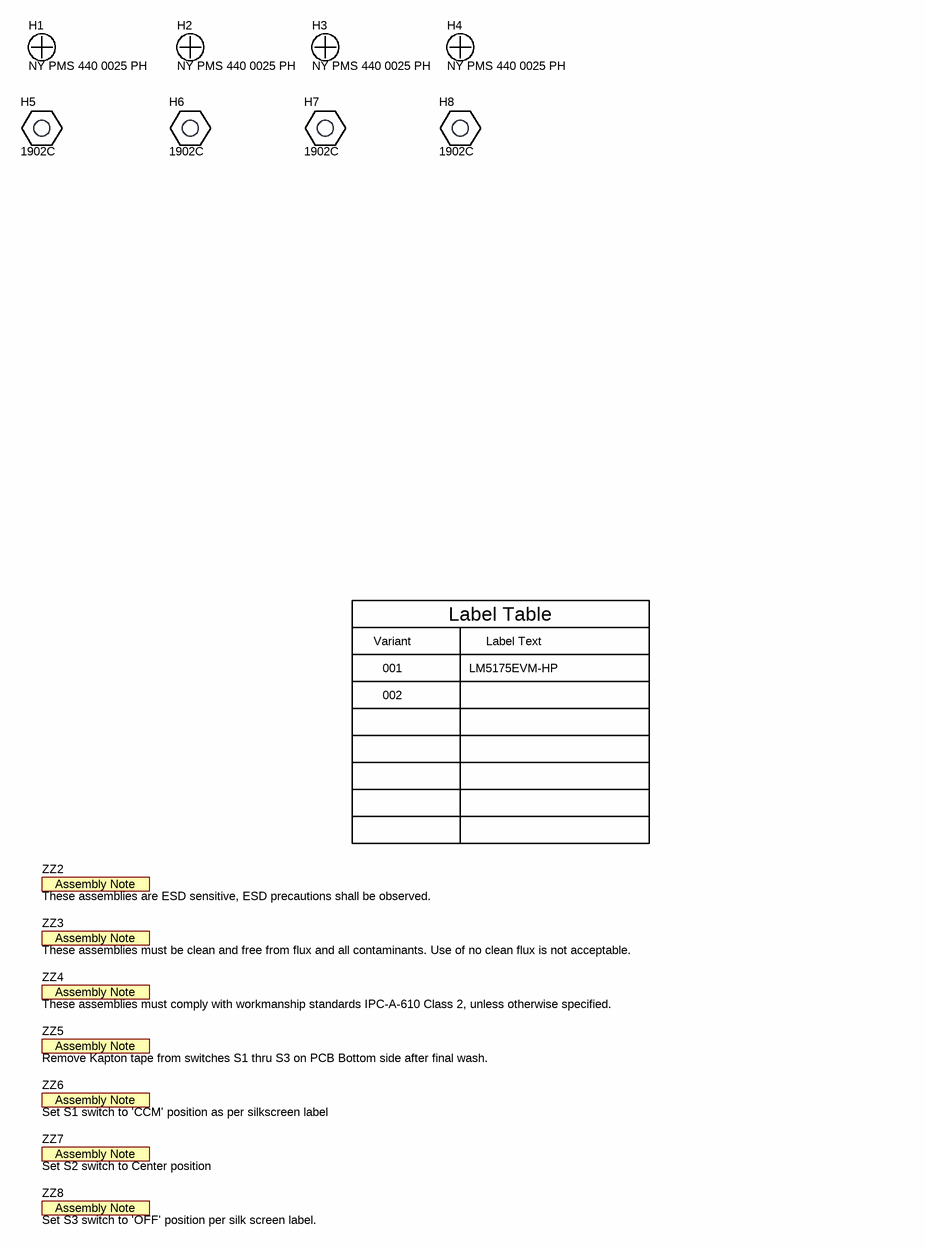
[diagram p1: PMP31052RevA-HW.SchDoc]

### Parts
H1  NY PMS 440 0025 PH  [NY PMS 440 0025 PH]
H2  NY PMS 440 0025 PH  [NY PMS 440 0025 PH]
H3  NY PMS 440 0025 PH  [NY PMS 440 0025 PH]
H4  NY PMS 440 0025 PH  [NY PMS 440 0025 PH]
H5  1902C  [Keystone_1902C]
H6  1902C  [Keystone_1902C]
H7  1902C  [Keystone_1902C]
H8  1902C  [Keystone_1902C]
ZZ2  These assemblies are ESD sensitive, ESD precautions shall be observed.  [AssemblyNote]  (no BOM)
ZZ3  These assemblies must be clean and free from flux and all contaminants. Use of no clean flux is not acceptable.  [AssemblyNote]  (no BOM)
ZZ4  These assemblies must comply with workmanship standards IPC-A-610 Class 2, unless otherwise specified.  [AssemblyNote]  (no BOM)
ZZ5  Remove Kapton tape from switches S1 thru S3 on PCB Bottom side after final wash.  [AssemblyNote]  (no BOM)
ZZ6  Set S1 switch to 'CCM' position as per silkscreen label  [AssemblyNote]  (no BOM)
ZZ7  Set S2 switch to Center position  [AssemblyNote]  (no BOM)
ZZ8  Set S3 switch to 'OFF' position per silk screen label.  [AssemblyNote]  (no BOM)

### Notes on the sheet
- Variant
- Label Table
- Label Text
- 001
- 002
- LM5175EVM-HP

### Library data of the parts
H1-H4 = NY PMS 440 0025 PH: Machine Screw, Round, #4-40 x 1/4, Nylon, Philips panhead; Manufacturer: B&F Fastener Supply; CompType: Hardware; SymbolCreator: codlsc; U/M: EA
H5-H8 = 1902C: Standoff, Hex, 0.5"L #4-40 Nylon; Manufacturer: Keystone; CompType: Hardware; SymbolCreator: a0412235
ZZ2-ZZ8 = AssemblyNote: SymbolCreator: codlsc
